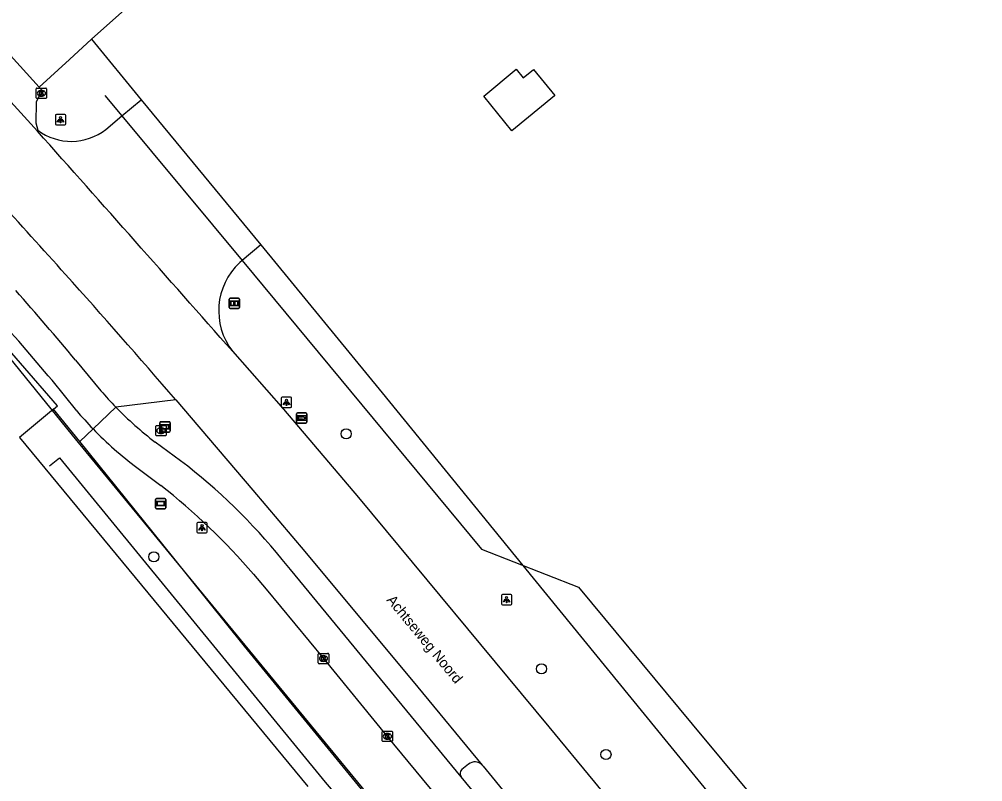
# Model space of a CAD drawing. Extents: x 156141 to 158132, y 385651 to 388399.
# Drawn here: x 157050.6 to 157143.7, y 387102.5 to 387176.2 of the extents above; entities that cross this region are included whole.
import ezdxf

# ---------------------------------------------------------------- set-up
doc = ezdxf.new("R2010")
doc.units = 0
for name, color, linetype in [('IMGEO_Berm_gesloten', 7, 'Continuous'), ('IMGEO_Berm_groen', 7, 'Continuous'), ('IMGEO_Boom', 7, 'Continuous'), ('IMGEO_Brandkraan', 7, 'Continuous'), ('IMGEO_Erf', 7, 'Continuous'), ('IMGEO_Fietspad_gesloten', 7, 'Continuous'), ('IMGEO_Hek', 7, 'Continuous'), ('IMGEO_Informatiebord', 7, 'Continuous'), ('IMGEO_Kolk', 7, 'Continuous'), ('IMGEO_Lichtpunt', 7, 'Continuous'), ('IMGEO_Openbare_ruimte_label', 7, 'Continuous'), ('IMGEO_Pand', 7, 'Continuous'), ('IMGEO_Rijbaan_lokaal_gesloten', 7, 'Continuous'), ('IMGEO_Rijbaan_lokaal_open', 7, 'Continuous'), ('IMGEO_Verklikker', 7, 'Continuous'), ('IMGEO_Wegwijzer', 7, 'Continuous')]:
    doc.layers.add(name, color=color, linetype=linetype)

msp = doc.modelspace()

# ---------------------------------------------------------------- linework, layer by layer
at = {"layer": 'IMGEO_Berm_gesloten'}
msp.add_lwpolyline([(157094.037, 387104.224), (157093.394, 387103.696)], dxfattribs=at)
for centre, radius, start, end in [((157094.642, 387103.44), 0.99, 43.9845, 127.68364), ((157093.749, 387103.305), 0.528, 132.21497, 216.98827)]:
    msp.add_arc(centre, radius, start, end, dxfattribs=at)
at = {"layer": 'IMGEO_Berm_groen'}
for points in [[(157052.568, 387169.626), (157055.477, 387172.297), (157057.621, 387174.266)], [(157057.621, 387174.266), (157062.426, 387168.42)], [(157073.956, 387154.391), (157085.704, 387140.096), (157099.287, 387123.425), (157113.294, 387106.234), (157117.052, 387101.622), (157133.358, 387082.049)], [(157241.165, 386912.065), (157168.24, 387000), (157137.214, 387037.654), (157129.348, 387046.654), (157129.178, 387046.529), (157127.008, 387049.143), (157127.143, 387049.253), (157124.865, 387052.05), (157124.727, 387051.938), (157091.865, 387091.792), (157084.853, 387100.371), (157072.384, 387115.628), (157065.427, 387124.277), (157056.488, 387135.39)]]:
    msp.add_lwpolyline(points, dxfattribs=at)
at = {"layer": 'IMGEO_Boom'}
for centre in [(157082.215, 387136.132), (157063.641, 387124.246), (157101.094, 387113.426), (157107.32, 387105.15)]:
    msp.add_circle(centre, 0.489, dxfattribs=at)
at = {"layer": 'IMGEO_Brandkraan'}
for p, q in [((157063.825, 387136.015), (157063.825, 387136.867)), ((157063.9, 387136.941), (157064.752, 387136.941)), ((157064.313, 387136.721), (157064.338, 387136.721)), ((157064.826, 387136.867), (157064.826, 387136.015)), ((157064.752, 387135.941), (157063.9, 387135.941)), ((157064.336, 387136.161), (157064.311, 387136.161))]:
    msp.add_line(p, q, dxfattribs=at)
for points in [[(157063.825, 387136.015), (157063.825, 387136.867)], [(157063.9, 387136.941), (157064.752, 387136.941)], [(157064.173, 387136.641), (157064.173, 387136.241), (157064.386, 387136.241)], [(157064.404, 387136.641), (157064.173, 387136.641)], [(157064.352, 387136.56), (157064.298, 387136.56), (157064.298, 387136.484)], [(157064.298, 387136.484), (157064.351, 387136.484)], [(157064.36, 387136.408), (157064.298, 387136.408), (157064.298, 387136.327)], [(157064.298, 387136.327), (157064.36, 387136.327)], [(157064.826, 387136.867), (157064.826, 387136.015)], [(157064.752, 387135.941), (157063.9, 387135.941)]]:
    msp.add_lwpolyline(points, dxfattribs=at)
for centre, radius, start, end in [((157063.902, 387136.865), 0.0765, 91.55205, 178.44795), ((157063.902, 387136.865), 0.0765, 91.55205, 178.44795), ((157064.353, 387136.522), 0.0379, 267.82845, 90.93552), ((157064.361, 387136.367), 0.0404, 269.87594, 90.50774), ((157064.408, 387136.496), 0.145, 59.4692, 91.53667), ((157064.433, 387136.543), 0.0922, 285.51372, 58.15012), ((157064.438, 387136.351), 0.105, 301.31148, 78.98903), ((157064.75, 387136.865), 0.0765, 1.55205, 88.44795), ((157064.75, 387136.865), 0.0765, 1.55205, 88.44795), ((157063.902, 387136.017), 0.0765, 181.55205, 268.44795), ((157063.902, 387136.017), 0.0765, 181.55205, 268.44795), ((157064.392, 387136.492), 0.251, 268.66757, 293.53466), ((157064.75, 387136.017), 0.0765, 271.55205, 358.44795), ((157064.75, 387136.017), 0.0765, 271.55205, 358.44795)]:
    msp.add_arc(centre, radius, start, end, dxfattribs=at)
for centre, major_axis, ratio, start_param, end_param in [((157064.312, 387136.441), (-0.387, 0.002), 0.722429, 4.712389, 7.853982), ((157064.337, 387136.441), (-0.39, 0.002), 0.717154, 1.570796, 4.712389)]:
    msp.add_ellipse(centre, major_axis=major_axis, ratio=ratio, start_param=start_param, end_param=end_param, dxfattribs=at)
at = {"layer": 'IMGEO_Erf'}
for points in [[(157057.621, 387174.266), (157112.914, 387223.48)], [(157053.949, 387138.526), (157050.664, 387135.786), (157078.507, 387102.046)]]:
    msp.add_lwpolyline(points, dxfattribs=at)
at = {"layer": 'IMGEO_Fietspad_gesloten'}
for points in [[(157059.971, 387138.696), (157057.764, 387136.601)], [(157066.225, 387133.531), (157063.751, 387135.337)], [(157062.004, 387132.869), (157064.32, 387131.149)], [(157093.327, 387102.987), (157076.849, 387123.021), (157076.031, 387123.995)], [(157073.27, 387122.584), (157074.475, 387121.125), (157080.024, 387114.424), (157086.194, 387106.902), (157095.114, 387096.083), (157108.208, 387080.174), (157121.465, 387064.047), (157133.334, 387049.652), (157140.75, 387040.623), (157148.425, 387031.279), (157148.541, 387031.183), (157148.691, 387031.016), (157154.778, 387023.638)], [(157100.595, 387094.175), (157093.327, 387102.987)]]:
    msp.add_lwpolyline(points, dxfattribs=at)
for centre, radius, start, end in [((157086.472, 387164.713), 37.137, 224.47108, 232.27878), ((157082.16, 387160.043), 33.833, 223.85774, 233.43452), ((157031.382, 387087.891), 57.42, 38.95919, 52.64032), ((157022.304, 387078.285), 67.527, 40.99633, 51.52212)]:
    msp.add_arc(centre, radius, start, end, dxfattribs=at)
at = {"layer": 'IMGEO_Hek'}
for points in [[(157057.621, 387174.266), (157112.914, 387223.48)], [(157058.901, 387168.831), (157060.551, 387166.844), (157072.154, 387152.871), (157095.305, 387124.991)], [(157056.366, 387135.293), (157056.202, 387135.492), (157047.216, 387146.552), (157045.489, 387148.678), (157045.548, 387148.73)], [(157083.17, 387098.968), (157084.993, 387100.488), (157056.366, 387135.293)], [(157053.553, 387133.028), (157054.516, 387133.828), (157080.175, 387102.467), (157090.407, 387090.578), (157091.865, 387091.792), (157124.727, 387051.938)], [(157095.305, 387124.991), (157104.658, 387121.314), (157115.634, 387108.084)], [(157115.634, 387108.084), (157118.497, 387104.633)], [(157118.497, 387104.633), (157121.698, 387100.785)]]:
    msp.add_lwpolyline(points, dxfattribs=at)
at = {"layer": 'IMGEO_Informatiebord'}
for p, q in [((157070.91, 387148.341), (157070.91, 387149.141)), ((157070.91, 387149.141), (157070.91, 387148.341)), ((157071.01, 387149.241), (157071.8, 387149.241)), ((157071.8, 387149.241), (157071.01, 387149.241)), ((157071.9, 387149.141), (157071.9, 387148.341)), ((157071.9, 387148.341), (157071.9, 387149.141)), ((157071.8, 387148.241), (157071.01, 387148.241)), ((157071.01, 387148.241), (157071.8, 387148.241))]:
    msp.add_line(p, q, dxfattribs=at)
for points in [[(157071.011, 387148.973), (157071.799, 387148.973), (157071.799, 387148.509), (157071.011, 387148.509), (157071.011, 387148.973)], [(157071.076, 387148.908), (157071.076, 387148.574), (157071.351, 387148.574), (157071.352, 387148.787), (157071.456, 387148.788), (157071.457, 387148.574), (157071.734, 387148.574), (157071.734, 387148.908), (157071.458, 387148.908), (157071.458, 387148.828), (157071.352, 387148.828), (157071.352, 387148.908), (157071.076, 387148.908)]]:
    msp.add_lwpolyline(points, dxfattribs=at)
for centre, start, end in [((157071.01, 387149.141), 90, 180), ((157071.01, 387149.141), 90, 180), ((157071.8, 387149.141), 0, 90), ((157071.8, 387149.141), 360, 90), ((157071.01, 387148.341), 180, 270), ((157071.01, 387148.341), 180, 270), ((157071.8, 387148.341), 270, 0), ((157071.8, 387148.341), 270, 0)]:
    msp.add_arc(centre, 0.1, start, end, dxfattribs=at)
at = {"layer": 'IMGEO_Kolk'}
for p, q in [((157052.266, 387168.614), (157052.266, 387169.466)), ((157052.341, 387169.54), (157053.193, 387169.54)), ((157052.754, 387169.32), (157052.779, 387169.32)), ((157053.267, 387169.466), (157053.267, 387168.614)), ((157053.193, 387168.54), (157052.341, 387168.54)), ((157052.777, 387168.76), (157052.752, 387168.76)), ((157079.601, 387114.923), (157080.453, 387114.923)), ((157079.526, 387113.997), (157079.526, 387114.849)), ((157080.037, 387114.143), (157080.012, 387114.143)), ((157080.014, 387114.703), (157080.039, 387114.703)), ((157080.527, 387114.849), (157080.527, 387113.997)), ((157080.453, 387113.923), (157079.601, 387113.923)), ((157085.696, 387106.475), (157085.696, 387107.327)), ((157085.771, 387107.401), (157086.623, 387107.401)), ((157086.207, 387106.621), (157086.182, 387106.621)), ((157086.184, 387107.181), (157086.209, 387107.181)), ((157086.697, 387107.327), (157086.697, 387106.475)), ((157086.623, 387106.401), (157085.771, 387106.401))]:
    msp.add_line(p, q, dxfattribs=at)
for points in [[(157052.266, 387168.614), (157052.266, 387169.466)], [(157052.341, 387169.54), (157053.193, 387169.54)], [(157052.587, 387169.24), (157052.71, 387169.24), (157052.71, 387169.089), (157052.84, 387169.24), (157053.004, 387169.24), (157052.858, 387169.089), (157053.011, 387168.84), (157052.859, 387168.84), (157052.774, 387169.004), (157052.71, 387168.937), (157052.71, 387168.84), (157052.587, 387168.84), (157052.587, 387169.24)], [(157053.267, 387169.466), (157053.267, 387168.614)], [(157053.193, 387168.54), (157052.341, 387168.54)], [(157079.601, 387114.923), (157080.453, 387114.923)], [(157079.526, 387113.997), (157079.526, 387114.849)], [(157079.847, 387114.623), (157079.97, 387114.623), (157079.97, 387114.472), (157080.1, 387114.623), (157080.264, 387114.623), (157080.118, 387114.472), (157080.271, 387114.223), (157080.119, 387114.223), (157080.034, 387114.387), (157079.97, 387114.32), (157079.97, 387114.223), (157079.847, 387114.223), (157079.847, 387114.623)], [(157080.527, 387114.849), (157080.527, 387113.997)], [(157080.453, 387113.923), (157079.601, 387113.923)], [(157085.696, 387106.475), (157085.696, 387107.327)], [(157085.771, 387107.401), (157086.623, 387107.401)], [(157086.017, 387107.101), (157086.14, 387107.101), (157086.14, 387106.95), (157086.27, 387107.101), (157086.434, 387107.101), (157086.288, 387106.95), (157086.441, 387106.701), (157086.289, 387106.701), (157086.204, 387106.865), (157086.14, 387106.798), (157086.14, 387106.701), (157086.017, 387106.701), (157086.017, 387107.101)], [(157086.697, 387107.327), (157086.697, 387106.475)], [(157086.623, 387106.401), (157085.771, 387106.401)]]:
    msp.add_lwpolyline(points, dxfattribs=at)
for centre, start, end in [((157052.343, 387169.464), 91.55205, 178.44795), ((157052.343, 387169.464), 91.55205, 178.44795), ((157053.191, 387169.464), 1.55205, 88.44795), ((157053.191, 387169.464), 1.55205, 88.44795), ((157052.343, 387168.616), 181.55205, 268.44795), ((157052.343, 387168.616), 181.55205, 268.44795), ((157053.191, 387168.616), 271.55205, 358.44795), ((157053.191, 387168.616), 271.55205, 358.44795), ((157079.603, 387114.847), 91.55205, 178.44795), ((157079.603, 387114.847), 91.55205, 178.44795), ((157080.451, 387114.847), 1.55205, 88.44795), ((157080.451, 387114.847), 1.55205, 88.44795), ((157079.603, 387113.999), 181.55205, 268.44795), ((157079.603, 387113.999), 181.55205, 268.44795), ((157080.451, 387113.999), 271.55205, 358.44795), ((157080.451, 387113.999), 271.55205, 358.44795), ((157085.773, 387107.325), 91.55205, 178.44795), ((157085.773, 387107.325), 91.55205, 178.44795), ((157086.621, 387107.325), 1.55205, 88.44795), ((157086.621, 387107.325), 1.55205, 88.44795), ((157085.773, 387106.477), 181.55205, 268.44795), ((157085.773, 387106.477), 181.55205, 268.44795), ((157086.621, 387106.477), 271.55205, 358.44795), ((157086.621, 387106.477), 271.55205, 358.44795)]:
    msp.add_arc(centre, 0.0765, start, end, dxfattribs=at)
for centre, major_axis, ratio, start_param, end_param in [((157052.753, 387169.04), (-0.387, 0.002), 0.722429, 4.712389, 7.853982), ((157052.778, 387169.04), (-0.39, 0.002), 0.717154, 1.570796, 4.712389), ((157080.013, 387114.423), (-0.387, 0.002), 0.722429, 4.712389, 7.853982), ((157080.038, 387114.423), (-0.39, 0.002), 0.717154, 1.570796, 4.712389), ((157086.183, 387106.901), (-0.387, 0.002), 0.722429, 4.712389, 7.853982), ((157086.208, 387106.901), (-0.39, 0.002), 0.717154, 1.570796, 4.712389)]:
    msp.add_ellipse(centre, major_axis=major_axis, ratio=ratio, start_param=start_param, end_param=end_param, dxfattribs=at)
at = {"layer": 'IMGEO_Lichtpunt'}
for p, q in [((157054.121, 387166.883), (157054.121, 387166.076)), ((157054.121, 387166.883), (157054.121, 387166.076)), ((157055.023, 387166.978), (157054.215, 387166.978)), ((157055.023, 387166.978), (157054.215, 387166.978)), ((157055.117, 387166.076), (157055.117, 387166.883)), ((157055.117, 387166.076), (157055.117, 387166.883)), ((157054.215, 387165.982), (157055.023, 387165.982)), ((157054.215, 387165.982), (157055.023, 387165.982)), ((157075.95, 387139.572), (157075.95, 387138.765)), ((157075.95, 387139.572), (157075.95, 387138.765)), ((157076.852, 387139.667), (157076.044, 387139.667)), ((157076.852, 387139.667), (157076.044, 387139.667)), ((157076.946, 387138.765), (157076.946, 387139.572)), ((157076.946, 387138.765), (157076.946, 387139.572)), ((157076.044, 387138.671), (157076.852, 387138.671)), ((157076.044, 387138.671), (157076.852, 387138.671)), ((157067.792, 387127.465), (157067.792, 387126.658)), ((157067.792, 387127.465), (157067.792, 387126.658)), ((157068.694, 387127.56), (157067.886, 387127.56)), ((157068.694, 387127.56), (157067.886, 387127.56)), ((157068.788, 387126.658), (157068.788, 387127.465)), ((157068.788, 387126.658), (157068.788, 387127.465)), ((157067.886, 387126.564), (157068.694, 387126.564)), ((157067.886, 387126.564), (157068.694, 387126.564)), ((157097.216, 387120.51), (157097.216, 387119.703)), ((157097.216, 387120.51), (157097.216, 387119.703)), ((157098.118, 387120.605), (157097.31, 387120.605)), ((157098.118, 387120.605), (157097.31, 387120.605)), ((157098.212, 387119.703), (157098.212, 387120.51)), ((157098.212, 387119.703), (157098.212, 387120.51)), ((157097.31, 387119.609), (157098.118, 387119.609)), ((157097.31, 387119.609), (157098.118, 387119.609))]:
    msp.add_line(p, q, dxfattribs=at)
for points in [[(157054.495, 387166.547), (157054.534, 387166.519), (157054.346, 387166.257), (157054.308, 387166.284), (157054.495, 387166.547)], [(157054.597, 387166.499), (157054.644, 387166.499), (157054.644, 387166.177), (157054.597, 387166.177), (157054.597, 387166.499)], [(157054.707, 387166.519), (157054.745, 387166.546), (157054.932, 387166.284), (157054.893, 387166.256), (157054.707, 387166.519)], [(157076.324, 387139.236), (157076.363, 387139.208), (157076.175, 387138.946), (157076.137, 387138.973), (157076.324, 387139.236)], [(157076.426, 387139.188), (157076.473, 387139.188), (157076.473, 387138.866), (157076.426, 387138.866), (157076.426, 387139.188)], [(157076.536, 387139.208), (157076.574, 387139.235), (157076.761, 387138.973), (157076.722, 387138.945), (157076.536, 387139.208)], [(157068.166, 387127.129), (157068.205, 387127.101), (157068.017, 387126.839), (157067.979, 387126.866), (157068.166, 387127.129)], [(157068.268, 387127.081), (157068.315, 387127.081), (157068.315, 387126.759), (157068.268, 387126.759), (157068.268, 387127.081)], [(157068.378, 387127.101), (157068.416, 387127.128), (157068.603, 387126.866), (157068.564, 387126.838), (157068.378, 387127.101)], [(157097.59, 387120.174), (157097.629, 387120.146), (157097.441, 387119.884), (157097.403, 387119.911), (157097.59, 387120.174)], [(157097.692, 387120.126), (157097.739, 387120.126), (157097.739, 387119.804), (157097.692, 387119.804), (157097.692, 387120.126)], [(157097.802, 387120.146), (157097.84, 387120.173), (157098.027, 387119.911), (157097.988, 387119.883), (157097.802, 387120.146)]]:
    msp.add_lwpolyline(points, dxfattribs=at)
for centre in [(157054.62, 387166.681), (157076.449, 387139.37), (157068.291, 387127.263), (157097.715, 387120.308)]:
    msp.add_circle(centre, 0.0994, dxfattribs=at)
for centre, start, end in [((157054.215, 387166.883), 90, 180), ((157054.215, 387166.883), 90, 180), ((157055.023, 387166.883), 0, 90), ((157055.023, 387166.883), 0, 90), ((157054.215, 387166.076), 180, 270), ((157054.215, 387166.076), 180, 270), ((157055.023, 387166.076), 270, 0), ((157055.023, 387166.076), 270, 360), ((157076.044, 387139.572), 90, 180), ((157076.044, 387139.572), 90, 180), ((157076.852, 387139.572), 0, 90), ((157076.852, 387139.572), 0, 90), ((157076.044, 387138.765), 180, 270), ((157076.044, 387138.765), 180, 270), ((157076.852, 387138.765), 270, 0), ((157076.852, 387138.765), 270, 360), ((157067.886, 387127.465), 90, 180), ((157067.886, 387127.465), 90, 180), ((157068.694, 387127.465), 0, 90), ((157068.694, 387127.465), 0, 90), ((157067.886, 387126.658), 180, 270), ((157067.886, 387126.658), 180, 270), ((157068.694, 387126.658), 270, 0), ((157068.694, 387126.658), 270, 360), ((157097.31, 387120.51), 90, 180), ((157097.31, 387120.51), 90, 180), ((157098.118, 387120.51), 0, 90), ((157098.118, 387120.51), 0, 90), ((157097.31, 387119.703), 180, 270), ((157097.31, 387119.703), 180, 270), ((157098.118, 387119.703), 270, 0), ((157098.118, 387119.703), 270, 360)]:
    msp.add_arc(centre, 0.0946, start, end, dxfattribs=at)
at = {"layer": 'IMGEO_Pand'}
msp.add_lwpolyline([(157102.331, 387168.784), (157098.239, 387165.419), (157095.505, 387168.744), (157098.634, 387171.362), (157099.327, 387170.534), (157100.301, 387171.349), (157102.371, 387168.817), (157102.331, 387168.784)], dxfattribs=at)
at = {"layer": 'IMGEO_Rijbaan_lokaal_gesloten'}
for points in [[(157044.624, 387173.91), (157048.511, 387169.641), (157052.393, 387165.368)], [(157071.23, 387144.111), (157076.164, 387138.508), (157083.422, 387129.976), (157101.791, 387107.807), (157106.198, 387102.464), (157123.421, 387081.401)], [(157065.75, 387139.413), (157067.235, 387137.684), (157073.21, 387130.7), (157078.233, 387124.756), (157089.15, 387111.653), (157095.355, 387104.128)], [(157095.355, 387104.128), (157095.454, 387104.008), (157102.51, 387095.375)]]:
    msp.add_lwpolyline(points, dxfattribs=at)
for centre, radius, start, end in [((152939.918, 383502.102), 5507.446, 41.398183, 41.693662), ((156458.577, 386617.025), 800.964, 41.861384, 42.568194), ((156453.38, 386612.303), 807.986, 40.720898, 41.864799)]:
    msp.add_arc(centre, radius, start, end, dxfattribs=at)
at = {"layer": 'IMGEO_Rijbaan_lokaal_open'}
for points in [[(157048.291, 387174.308), (157048.528, 387174.052), (157052.568, 387169.626)], [(157052.568, 387169.626), (157052.949, 387169.206), (157052.576, 387168.865), (157052.28, 387168.18), (157052.217, 387166.182), (157052.412, 387165.473)], [(157059, 387165.541), (157060.551, 387166.844), (157062.426, 387168.42)], [(157062.426, 387168.42), (157073.956, 387154.391)], [(157053.949, 387138.526), (157054.316, 387138.824), (157047.156, 387147.091), (157045.589, 387148.768), (157045.548, 387148.73), (157039.884, 387154.835)], [(157073.956, 387154.391), (157072.154, 387152.871), (157071.93, 387152.682)], [(157056.077, 387143.258), (157058.516, 387140.301)], [(157056.179, 387138.368), (157053.795, 387141.315)], [(157065.75, 387139.413), (157059.971, 387138.696)], [(157056.488, 387135.39), (157053.949, 387138.526)], [(157057.764, 387136.601), (157056.488, 387135.39)]]:
    msp.add_lwpolyline(points, dxfattribs=at)
for centre, radius, start, end in [((157055.661, 387169.826), 5.432, 233.2603, 307.92245), ((157076.282, 387148.012), 6.383, 132.98685, 217.67509), ((156696.817, 386841.024), 469.482, 40.07284, 41.15498), ((156661.267, 386808.379), 514.709, 40.3041, 41.28397), ((157091.795, 387169.008), 43.95, 220.7814, 223.60586), ((157082.474, 387160.36), 34.279, 219.90796, 223.87629)]:
    msp.add_arc(centre, radius, start, end, dxfattribs=at)
at = {"layer": 'IMGEO_Verklikker'}
for p, q in [((157064.314, 387137.308), (157065.104, 387137.308)), ((157065.104, 387137.308), (157064.314, 387137.308)), ((157064.214, 387136.408), (157064.214, 387137.208)), ((157064.214, 387137.208), (157064.214, 387136.408)), ((157065.204, 387137.208), (157065.204, 387136.408)), ((157065.204, 387136.408), (157065.204, 387137.208)), ((157065.104, 387136.308), (157064.314, 387136.308)), ((157064.314, 387136.308), (157065.104, 387136.308)), ((157063.902, 387129.896), (157064.692, 387129.896)), ((157064.692, 387129.896), (157063.902, 387129.896)), ((157063.802, 387128.996), (157063.802, 387129.796)), ((157063.802, 387129.796), (157063.802, 387128.996)), ((157064.692, 387128.896), (157063.902, 387128.896)), ((157063.902, 387128.896), (157064.692, 387128.896)), ((157064.792, 387129.796), (157064.792, 387128.996)), ((157064.792, 387128.996), (157064.792, 387129.796))]:
    msp.add_line(p, q, dxfattribs=at)
for points in [[(157064.315, 387137.04), (157065.103, 387137.04), (157065.103, 387136.576), (157064.315, 387136.576), (157064.315, 387137.04)], [(157064.38, 387136.975), (157064.38, 387136.641), (157065.038, 387136.641), (157065.038, 387136.975), (157064.38, 387136.975)], [(157063.903, 387129.628), (157064.691, 387129.628), (157064.691, 387129.164), (157063.903, 387129.164), (157063.903, 387129.628)], [(157063.968, 387129.563), (157063.968, 387129.229), (157064.626, 387129.229), (157064.626, 387129.563), (157063.968, 387129.563)]]:
    msp.add_lwpolyline(points, dxfattribs=at)
for centre, start, end in [((157064.314, 387137.208), 90, 180), ((157064.314, 387137.208), 90, 180), ((157065.104, 387137.208), 0, 90), ((157065.104, 387137.208), 360, 90), ((157064.314, 387136.408), 180, 270), ((157064.314, 387136.408), 180, 270), ((157065.104, 387136.408), 270, 0), ((157065.104, 387136.408), 270, 0), ((157063.902, 387129.796), 90, 180), ((157063.902, 387129.796), 90, 180), ((157064.692, 387129.796), 0, 90), ((157064.692, 387129.796), 360, 90), ((157063.902, 387128.996), 180, 270), ((157063.902, 387128.996), 180, 270), ((157064.692, 387128.996), 270, 0), ((157064.692, 387128.996), 270, 0)]:
    msp.add_arc(centre, 0.1, start, end, dxfattribs=at)
at = {"layer": 'IMGEO_Wegwijzer'}
for p, q in [((157077.417, 387137.262), (157077.417, 387138.062)), ((157077.417, 387138.062), (157077.417, 387137.262)), ((157077.517, 387138.162), (157078.307, 387138.162)), ((157078.307, 387138.162), (157077.517, 387138.162)), ((157078.407, 387138.062), (157078.407, 387137.262)), ((157078.407, 387137.262), (157078.407, 387138.062)), ((157078.307, 387137.162), (157077.517, 387137.162)), ((157077.517, 387137.162), (157078.307, 387137.162))]:
    msp.add_line(p, q, dxfattribs=at)
for points in [[(157077.518, 387137.894), (157078.306, 387137.894), (157078.306, 387137.43), (157077.518, 387137.43), (157077.518, 387137.894)], [(157077.583, 387137.746), (157077.583, 387137.662), (157077.583, 387137.578), (157077.994, 387137.578), (157077.994, 387137.495), (157078.241, 387137.662), (157077.994, 387137.829), (157077.994, 387137.746), (157077.583, 387137.746)]]:
    msp.add_lwpolyline(points, dxfattribs=at)
for centre, start, end in [((157077.517, 387138.062), 90, 180), ((157077.517, 387138.062), 90, 180), ((157077.517, 387137.262), 180, 270), ((157077.517, 387137.262), 180, 270), ((157078.307, 387138.062), 0, 90), ((157078.307, 387138.062), 360, 90), ((157078.307, 387137.262), 270, 0), ((157078.307, 387137.262), 270, 0)]:
    msp.add_arc(centre, 0.1, start, end, dxfattribs=at)

# ---------------------------------------------------------------- texts
at = {"layer": 'IMGEO_Openbare_ruimte_label'}
msp.add_text('Achtseweg Noord', height=1, rotation=309.48286, dxfattribs=at).set_placement((157086.07, 387120.05))

doc.saveas('drawing.dxf')
